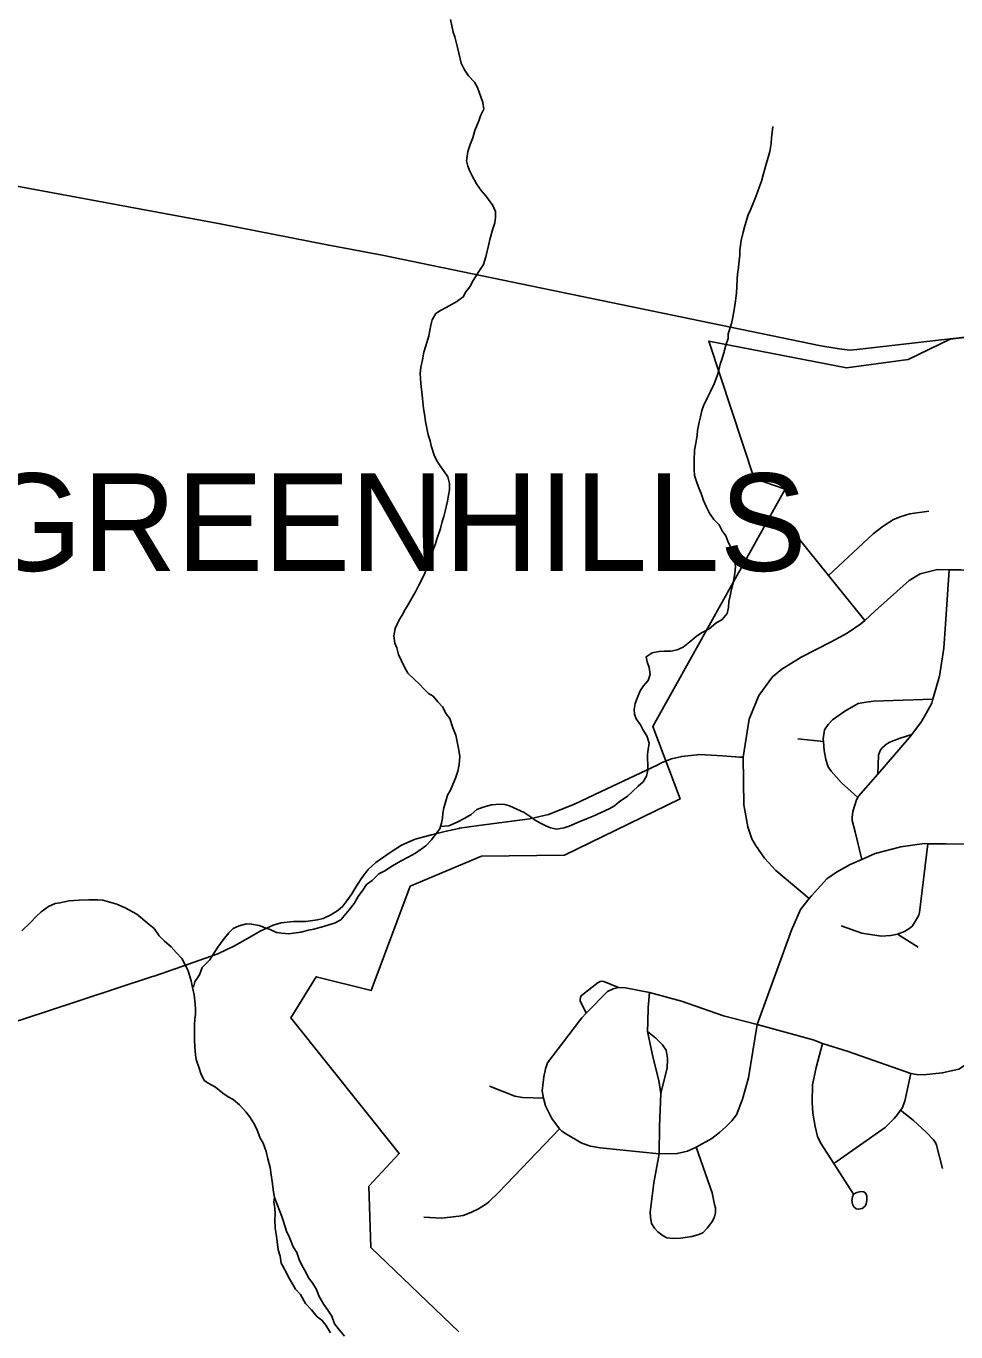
# Model space of a CAD drawing. Extents: x 0 to 34, y 0 to 22.
# Drawn here: x 6.973 to 7.876, y 18.138 to 19.407 of the extents above; entities that cross this region are included whole.
import ezdxf

# ---------------------------------------------------------------- set-up
doc = ezdxf.new("R2010")
doc.units = 0
for name, color, linetype in [('GM_X_City_Street', 7, 'Continuous'), ('GM_X_Corporation', 7, 'Continuous'), ('GM_X_Corporation_Text', 7, 'Continuous'), ('GM_X_County_Road', 7, 'Continuous'), ('GM_X_Major_Lake', 7, 'Continuous'), ('GM_X_Minor_River', 7, 'Continuous')]:
    doc.layers.add(name, color=color, linetype=linetype)

msp = doc.modelspace()

# ---------------------------------------------------------------- linework, layer by layer
at = {"layer": 'GM_X_City_Street'}
for points in [[(6.7657, 19.288), (7.1613, 19.2149), (7.265, 19.1946), (7.3185, 19.1843), (7.7448, 19.0962), (7.7625, 19.0934), (7.7731, 19.0923), (7.7798, 19.0928), (7.9442, 19.1116)], [(7.7524, 18.8732), (7.7958, 18.9137), (7.8055, 18.9212), (7.8155, 18.9276), (7.8229, 18.9305), (7.8313, 18.9332), (7.8496, 18.9357)], [(7.7875, 18.8296), (7.7524, 18.8732), (7.7122, 18.9231)], [(7.6692, 18.6966), (7.6752, 18.7335), (7.6847, 18.7567), (7.6977, 18.7746), (7.707, 18.7823), (7.7256, 18.7939), (7.7549, 18.8086), (7.7703, 18.8172), (7.7838, 18.8263), (7.7875, 18.8296), (7.7975, 18.8388), (7.8306, 18.8682), (7.8414, 18.8747), (7.8582, 18.8791), (7.8695, 18.8787), (7.8807, 18.8787), (7.8947, 18.8772), (7.9195, 18.8749)], [(7.7847, 18.5973), (7.7781, 18.6241), (7.7753, 18.6352), (7.7753, 18.638), (7.776, 18.6437), (7.7778, 18.65), (7.7796, 18.6551), (7.7808, 18.6574), (7.7815, 18.6586), (7.8001, 18.6801), (7.8306, 18.7153), (7.8331, 18.7186), (7.8425, 18.7313), (7.8476, 18.7397), (7.8525, 18.7492), (7.8537, 18.7531), (7.8602, 18.7753), (7.8644, 18.8025), (7.8659, 18.826), (7.8695, 18.8787)], [(7.7808, 18.6574), (7.7648, 18.6717), (7.7548, 18.6832), (7.752, 18.6873), (7.7498, 18.6944), (7.7479, 18.703), (7.7473, 18.7118), (7.7471, 18.7144), (7.7485, 18.7231), (7.7519, 18.7284), (7.756, 18.7328), (7.7681, 18.7415), (7.7812, 18.7487), (7.7889, 18.7502), (7.796, 18.751), (7.8537, 18.7531)], [(7.8001, 18.6801), (7.8008, 18.6985), (7.8025, 18.7031), (7.8045, 18.7058), (7.809, 18.7096), (7.8118, 18.7112), (7.8167, 18.7132), (7.8219, 18.7152), (7.8331, 18.7186)], [(7.7225, 18.7144), (7.7473, 18.7118)], [(7.5998, 18.6951), (7.6096, 18.6973), (7.6272, 18.6994), (7.6491, 18.698), (7.6662, 18.6968), (7.6692, 18.6966), (7.6692, 18.6966)], [(7.7335, 18.5592), (7.7011, 18.5865), (7.6899, 18.5984), (7.6813, 18.611), (7.6778, 18.6173), (7.6739, 18.6291), (7.67, 18.6502), (7.6692, 18.6966)], [(7.683, 18.437), (7.7164, 18.5286), (7.725, 18.5485), (7.7335, 18.5592), (7.7356, 18.5619), (7.7505, 18.5785), (7.7599, 18.585), (7.7733, 18.5923), (7.7847, 18.5973), (7.7976, 18.603), (7.8224, 18.6094), (7.8453, 18.6126), (7.8487, 18.6125), (7.8665, 18.6123), (7.8925, 18.612)], [(7.7647, 18.5329), (7.7846, 18.5255), (7.8035, 18.5226), (7.8129, 18.5234), (7.8193, 18.5247), (7.8262, 18.5271), (7.8314, 18.5305), (7.834, 18.5327), (7.8365, 18.5368), (7.8401, 18.5432), (7.8408, 18.5458), (7.8487, 18.6125)], [(7.8193, 18.5247), (7.8395, 18.512)], [(7.5169, 18.4478), (7.5111, 18.4599), (7.511, 18.461), (7.5112, 18.4633), (7.5123, 18.4652), (7.5283, 18.4777), (7.5304, 18.4787), (7.5326, 18.4789), (7.5338, 18.4786), (7.5481, 18.4728)], [(7.683, 18.437), (7.6501, 18.4454), (7.6095, 18.4596), (7.5783, 18.4681), (7.5549, 18.4726), (7.5481, 18.4728), (7.5429, 18.4715), (7.5374, 18.469), (7.5169, 18.4478), (7.5127, 18.4435), (7.5103, 18.4403)], [(7.5876, 18.3112), (7.5879, 18.3378), (7.5893, 18.3697), (7.5874, 18.3823), (7.582, 18.4041), (7.5764, 18.4301), (7.5767, 18.4396), (7.5771, 18.4533), (7.5783, 18.4681)], [(7.5103, 18.4403), (7.5102, 18.4403), (7.4791, 18.3996), (7.4773, 18.3938), (7.4756, 18.386), (7.4739, 18.3724), (7.4753, 18.3653), (7.4774, 18.3578), (7.4835, 18.3455), (7.4908, 18.3354), (7.4932, 18.3333), (7.4978, 18.3302), (7.5127, 18.3214), (7.521, 18.3188), (7.5304, 18.3171), (7.5876, 18.3112), (7.6053, 18.3114), (7.6153, 18.3137), (7.6237, 18.3177), (7.6388, 18.326), (7.6464, 18.3318), (7.6524, 18.3373), (7.6584, 18.3434), (7.6627, 18.3492), (7.6688, 18.3642), (7.6744, 18.385), (7.683, 18.437)], [(7.683, 18.437), (7.7372, 18.4219), (7.7464, 18.4185), (7.7712, 18.4106), (7.8324, 18.3894), (7.8378, 18.3882), (7.8444, 18.3878), (7.8627, 18.3899), (7.8788, 18.3936), (7.9083, 18.4129)], [(7.5893, 18.3697), (7.5955, 18.3947), (7.5959, 18.403), (7.5959, 18.4043), (7.5945, 18.4118), (7.5908, 18.417), (7.5844, 18.4237), (7.5764, 18.4301)], [(7.7764, 18.272), (7.7798, 18.2735), (7.7835, 18.2745), (7.7867, 18.2742), (7.7886, 18.2727), (7.7894, 18.2699), (7.7895, 18.2661), (7.7889, 18.2627), (7.788, 18.2604), (7.7848, 18.2581), (7.7812, 18.2573), (7.7791, 18.2579), (7.7768, 18.2598), (7.7756, 18.2624), (7.775, 18.2659), (7.7755, 18.2693), (7.7764, 18.272), (7.7575, 18.3017), (7.7445, 18.322), (7.7417, 18.3281), (7.7393, 18.3378), (7.7371, 18.3508), (7.7363, 18.3614), (7.7368, 18.3781), (7.7403, 18.3951), (7.7464, 18.4185)], [(7.7575, 18.3017), (7.8072, 18.3368), (7.816, 18.3455), (7.8193, 18.3493), (7.8223, 18.3536), (7.8237, 18.3557), (7.8263, 18.3623), (7.8324, 18.3894)], [(7.4228, 18.3771), (7.4474, 18.3672), (7.455, 18.3658), (7.4753, 18.3653)], [(7.8223, 18.3536), (7.8344, 18.344), (7.8476, 18.3318), (7.854, 18.325), (7.8561, 18.3221), (7.8571, 18.3197), (7.8629, 18.2971)], [(7.3591, 18.2496), (7.3762, 18.2487), (7.3929, 18.2505), (7.3972, 18.2513), (7.4046, 18.2541), (7.4122, 18.2576), (7.4198, 18.2626), (7.4223, 18.2647), (7.432, 18.274), (7.4908, 18.3354)], [(7.5876, 18.3112), (7.5826, 18.2829), (7.5791, 18.2545), (7.5792, 18.2495), (7.5802, 18.2435), (7.5831, 18.2388), (7.5864, 18.2353), (7.5917, 18.2316), (7.595, 18.2297), (7.6017, 18.229), (7.6083, 18.2293), (7.6193, 18.2309), (7.6254, 18.2325), (7.63, 18.2344), (7.6344, 18.2388), (7.6395, 18.2458), (7.6415, 18.25), (7.6423, 18.2542), (7.6423, 18.2588), (7.6415, 18.2621), (7.6392, 18.2732), (7.6237, 18.3177)]]:
    msp.add_lwpolyline(points, dxfattribs=at)
at = {"layer": 'GM_X_Corporation'}
msp.add_lwpolyline([(8.8, 18.7458), (8.6784, 18.7536), (8.6177, 19.0337), (8.625, 19.1774), (7.9442, 19.1116), (7.8706, 19.1028), (7.8298, 19.0832), (7.7697, 19.0749), (7.636, 19.1009), (7.6799, 18.9673), (7.7101, 18.9572), (7.5816, 18.7265), (7.6081, 18.656), (7.4956, 18.6014), (7.4151, 18.6003), (7.3459, 18.5712), (7.308, 18.47), (7.2545, 18.4833), (7.2297, 18.4434), (7.3351, 18.3114), (7.3057, 18.2799), (7.3077, 18.2201), (7.3929, 18.1381)], dxfattribs=at)
at = {"layer": 'GM_X_County_Road'}
for points in [[(7.3929, 18.6274), (7.3936, 18.6275), (7.4126, 18.6301), (7.4621, 18.6368), (7.4803, 18.6408), (7.5055, 18.6511), (7.5313, 18.6634), (7.5857, 18.689), (7.5907, 18.6914), (7.5997, 18.6951), (7.5998, 18.6951)], [(7.0971, 18.484), (7.1173, 18.491), (7.1589, 18.5057), (7.1751, 18.5134), (7.1877, 18.5204), (7.1999, 18.5276), (7.2127, 18.5333), (7.2205, 18.5358), (7.2325, 18.5368), (7.2444, 18.537), (7.2558, 18.5386), (7.2611, 18.5399), (7.2687, 18.5433), (7.2756, 18.5477), (7.2803, 18.552), (7.2843, 18.5571), (7.289, 18.564), (7.2938, 18.5718), (7.2995, 18.5804), (7.3049, 18.5874), (7.3123, 18.5942), (7.3264, 18.6041), (7.3375, 18.611), (7.3506, 18.6169), (7.3665, 18.6213), (7.3795, 18.6245), (7.3929, 18.6274)], [(6.6748, 18.2683), (6.7285, 18.2655), (6.8486, 18.3747), (6.8655, 18.3843), (6.8923, 18.4031), (6.9436, 18.4327), (6.9578, 18.4383), (6.9913, 18.4492), (7.0954, 18.4834), (7.0971, 18.484)]]:
    msp.add_lwpolyline(points, dxfattribs=at)
at = {"layer": 'GM_X_Major_Lake'}
msp.add_lwpolyline([(7.2819, 18.1341), (7.2771, 18.1399), (7.2723, 18.1461), (7.2698, 18.1534), (7.2657, 18.1592), (7.262, 18.1649), (7.2572, 18.1726), (7.2544, 18.1799), (7.2507, 18.1861), (7.247, 18.1907), (7.2444, 18.1961), (7.2404, 18.203), (7.2378, 18.2084), (7.2357, 18.2153), (7.232, 18.2207), (7.2284, 18.2299), (7.2255, 18.236), (7.2227, 18.2456), (7.2212, 18.2502), (7.2165, 18.2621), (7.214, 18.2686), (7.2132, 18.2641), (7.2142, 18.2583), (7.2145, 18.253), (7.2143, 18.2469), (7.2146, 18.2389), (7.2156, 18.2332), (7.2162, 18.2286), (7.2175, 18.2179), (7.2193, 18.2118), (7.2203, 18.205), (7.2236, 18.1992), (7.2284, 18.1896), (7.2317, 18.1842), (7.2342, 18.1796), (7.2391, 18.1745), (7.2442, 18.1657), (7.2498, 18.1595), (7.2553, 18.1529), (7.2598, 18.1494), (7.2639, 18.1448), (7.2683, 18.1374)], dxfattribs=at)
at = {"layer": 'GM_X_Minor_River'}
for points in [[(7.3652, 19.0042), (7.3634, 19.0099), (7.3607, 19.0229), (7.3597, 19.0298), (7.3586, 19.0355), (7.3574, 19.0485), (7.3561, 19.0599), (7.3558, 19.0649), (7.3555, 19.0694), (7.356, 19.0755), (7.3577, 19.0827), (7.359, 19.0903), (7.3622, 19.1005), (7.3639, 19.1062), (7.366, 19.1164), (7.3672, 19.1217), (7.3708, 19.1277), (7.3754, 19.1306), (7.3808, 19.1336), (7.3865, 19.1369), (7.3911, 19.1395), (7.3973, 19.1439), (7.3997, 19.1488), (7.4036, 19.1537), (7.4071, 19.1597), (7.4126, 19.1687), (7.4169, 19.1755), (7.4193, 19.183), (7.4222, 19.1951), (7.4231, 19.1997), (7.426, 19.2099), (7.428, 19.2159), (7.4288, 19.2209), (7.4286, 19.2269), (7.426, 19.2327), (7.4194, 19.242), (7.4146, 19.2474), (7.4102, 19.2539), (7.4061, 19.2616), (7.4036, 19.2662), (7.4018, 19.2708), (7.4004, 19.2762), (7.4017, 19.2853), (7.4041, 19.2921), (7.4065, 19.2985), (7.4085, 19.3057), (7.4125, 19.3151), (7.4141, 19.3197), (7.4173, 19.3264), (7.4163, 19.3329), (7.4113, 19.3475), (7.4084, 19.3525), (7.4024, 19.3587), (7.3987, 19.3645), (7.3954, 19.371), (7.393, 19.3806), (7.3916, 19.3863), (7.3905, 19.3916), (7.3891, 19.3966), (7.3877, 19.4012), (7.3849, 19.4134)], [(7.6444, 19.0682), (7.6456, 19.0727), (7.6469, 19.0784), (7.6489, 19.0841), (7.6505, 19.0894), (7.6526, 19.0969), (7.6546, 19.1034), (7.6547, 19.1079), (7.6579, 19.1181), (7.6592, 19.1242), (7.6605, 19.1314), (7.6618, 19.1401), (7.6627, 19.1477), (7.6632, 19.1538), (7.6634, 19.161), (7.6638, 19.1659), (7.6647, 19.1724), (7.6656, 19.1792), (7.6661, 19.1841), (7.6662, 19.1895), (7.6667, 19.194), (7.6675, 19.1986), (7.6692, 19.2069), (7.6709, 19.213), (7.6741, 19.2235), (7.6765, 19.2284), (7.6801, 19.2371), (7.6821, 19.242), (7.6853, 19.2511), (7.6873, 19.2564), (7.6889, 19.2624), (7.6918, 19.273), (7.6934, 19.2783), (7.6951, 19.2851), (7.6964, 19.2931), (7.6969, 19.2988), (7.6974, 19.3037), (7.6983, 19.3094)], [(7.3753, 18.6292), (7.3834, 18.63), (7.3915, 18.6336), (7.3988, 18.6373), (7.4049, 18.6409), (7.4107, 18.6458), (7.4168, 18.6479), (7.4249, 18.6504), (7.4328, 18.651), (7.4378, 18.6505), (7.4423, 18.6493), (7.4566, 18.6429), (7.4615, 18.6398), (7.4667, 18.6359), (7.4723, 18.6324), (7.4776, 18.63), (7.4821, 18.628), (7.4878, 18.6267), (7.4954, 18.6281), (7.5003, 18.6295), (7.5099, 18.6339), (7.5172, 18.6368), (7.5237, 18.6393), (7.539, 18.6466), (7.5444, 18.6495), (7.549, 18.6533), (7.5571, 18.6588), (7.5618, 18.6633), (7.5672, 18.6685), (7.5722, 18.6726), (7.5754, 18.6782), (7.5766, 18.6839), (7.5767, 18.69), (7.5765, 18.6949), (7.5765, 18.6995), (7.577, 18.704), (7.5779, 18.7101), (7.5758, 18.7174), (7.5721, 18.7228), (7.5695, 18.7282), (7.5655, 18.7339), (7.5637, 18.7385), (7.5634, 18.7431), (7.5643, 18.7488), (7.5671, 18.7556), (7.5694, 18.7612), (7.5726, 18.7661), (7.5769, 18.771), (7.5789, 18.777), (7.5779, 18.7839), (7.5761, 18.7893), (7.5751, 18.7942), (7.5808, 18.7979), (7.5877, 18.7993), (7.5926, 18.7996), (7.5991, 18.7998), (7.6052, 18.8008), (7.6109, 18.8034), (7.6175, 18.8086), (7.6237, 18.8138), (7.6287, 18.8175), (7.6363, 18.8215), (7.6429, 18.8267), (7.649, 18.8304), (7.6537, 18.8364), (7.655, 18.8421), (7.6555, 18.8478), (7.6567, 18.8534), (7.658, 18.8599), (7.66, 18.8674), (7.6613, 18.8754), (7.6619, 18.8815), (7.6612, 18.888), (7.6584, 18.896), (7.6566, 18.9017), (7.6544, 18.9064), (7.6526, 18.9117), (7.6489, 18.9167), (7.646, 18.9225), (7.6408, 18.9275), (7.6367, 18.9337), (7.6338, 18.9395), (7.6309, 18.946), (7.6284, 18.9529), (7.6266, 18.9575), (7.6244, 18.9636), (7.6219, 18.9705), (7.6216, 18.9762), (7.6218, 18.9846), (7.622, 18.9949), (7.6233, 19.0017), (7.6246, 19.0093), (7.6251, 19.0142), (7.6267, 19.0222), (7.628, 19.0275), (7.6293, 19.0335), (7.6309, 19.038), (7.634, 19.0448), (7.6376, 19.052), (7.6412, 19.0595), (7.6444, 19.0682)], [(7.1354, 18.4733), (7.1367, 18.4782), (7.141, 18.485), (7.1438, 18.4921), (7.1511, 18.4996), (7.1539, 18.5045), (7.159, 18.512), (7.1641, 18.5191), (7.1695, 18.5258), (7.1738, 18.5303), (7.1795, 18.5329), (7.1868, 18.5346), (7.1917, 18.5345), (7.1989, 18.5332), (7.2049, 18.5308), (7.2098, 18.5292), (7.2158, 18.5264), (7.2211, 18.5256), (7.228, 18.5251), (7.2394, 18.5267), (7.247, 18.5285), (7.2523, 18.5295), (7.2615, 18.532), (7.2668, 18.5338), (7.2722, 18.5352), (7.2783, 18.5385), (7.2865, 18.5482), (7.2912, 18.5546), (7.2951, 18.5614), (7.2998, 18.5674), (7.3033, 18.573), (7.3087, 18.5767), (7.3153, 18.5834), (7.3211, 18.5863), (7.3287, 18.5911), (7.3364, 18.5955), (7.3437, 18.5996), (7.351, 18.6032), (7.361, 18.6106), (7.3665, 18.6162), (7.3711, 18.6226), (7.3747, 18.6271), (7.3763, 18.6324), (7.3771, 18.6373), (7.3776, 18.6422), (7.3785, 18.6475), (7.3801, 18.6528), (7.3821, 18.6596), (7.3849, 18.6645), (7.3873, 18.6702), (7.3897, 18.6762), (7.3921, 18.683), (7.3934, 18.6895), (7.3939, 18.6974), (7.3929, 18.7036), (7.3902, 18.7181), (7.3873, 18.7253), (7.3844, 18.7341), (7.3807, 18.7388), (7.3771, 18.7457), (7.3726, 18.7504), (7.3682, 18.7558), (7.3637, 18.7585), (7.3592, 18.7632), (7.3547, 18.7675), (7.3495, 18.7725), (7.3436, 18.7783), (7.3403, 18.7841), (7.3344, 18.7964), (7.3327, 18.8029), (7.3309, 18.8075), (7.3299, 18.8144), (7.3311, 18.8216), (7.3351, 18.8302), (7.3379, 18.8347), (7.341, 18.84), (7.3434, 18.8445), (7.3461, 18.849), (7.3512, 18.858), (7.354, 18.8633), (7.3596, 18.8746), (7.3636, 18.8852), (7.3652, 18.8901), (7.3684, 18.8992), (7.3704, 18.9041), (7.3716, 18.9086), (7.3753, 18.9188), (7.3769, 18.9256), (7.3785, 18.9305), (7.3798, 18.9358), (7.3819, 18.9453), (7.3831, 18.9513), (7.384, 18.9563), (7.3841, 18.9627), (7.3824, 18.9692), (7.3787, 18.9743), (7.3757, 18.9789), (7.3717, 18.9847), (7.3691, 18.99), (7.3663, 18.9992), (7.3652, 19.0042)], [(7.214, 18.2686), (7.213, 18.2743), (7.2117, 18.2842), (7.2107, 18.2907), (7.2097, 18.298), (7.2076, 18.3064), (7.2058, 18.3133), (7.2029, 18.3217), (7.2, 18.3263), (7.1968, 18.3351), (7.1935, 18.3413), (7.1898, 18.3474), (7.1861, 18.3521), (7.1798, 18.3587), (7.1738, 18.3641), (7.1689, 18.3665), (7.1637, 18.37), (7.1566, 18.3759), (7.1502, 18.3794), (7.1457, 18.3826), (7.1424, 18.3891), (7.1407, 18.3944), (7.1378, 18.4029), (7.1371, 18.4074), (7.1365, 18.4154), (7.1363, 18.4215), (7.1361, 18.4303), (7.1362, 18.4364), (7.1367, 18.4421), (7.1372, 18.4466), (7.1372, 18.4512), (7.137, 18.4569), (7.136, 18.4657), (7.1343, 18.4729), (7.1329, 18.4794), (7.13, 18.489), (7.1271, 18.4947), (7.1238, 18.5009), (7.1183, 18.5067), (7.1134, 18.5125), (7.1071, 18.518), (7.1019, 18.523), (7.0971, 18.53), (7.0922, 18.5342), (7.0803, 18.544), (7.0687, 18.5503), (7.0608, 18.5539), (7.0472, 18.5576), (7.0422, 18.5581), (7.0335, 18.5579), (7.024, 18.5577), (7.0145, 18.5571), (7.0054, 18.555), (7.0008, 18.5543), (6.9943, 18.5514), (6.9873, 18.5462), (6.9823, 18.5418), (6.9765, 18.5358), (6.9684, 18.528)]]:
    msp.add_lwpolyline(points, dxfattribs=at)

# ---------------------------------------------------------------- texts
at = {"layer": 'GM_X_Corporation_Text'}
msp.add_text('GREENHILLS', height=0.0947, rotation=0, dxfattribs=at).set_placement((6.9287, 18.8777))

doc.saveas('drawing.dxf')
